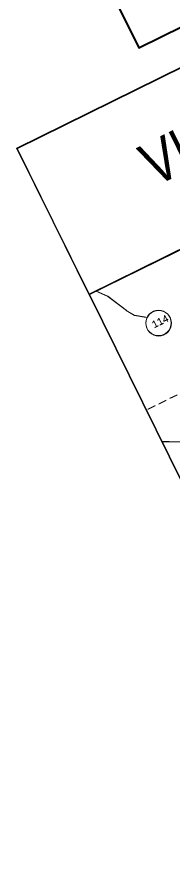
# Model space of a CAD drawing. Extents: x 2356606 to 2371222, y 6973096 to 6982644.
# Drawn here: x 2356946 to 2357060, y 6973388 to 6974009 of the extents above; entities that cross this region are included whole.
import ezdxf

# ---------------------------------------------------------------- set-up
doc = ezdxf.new("R2010")
doc.units = 0
doc.header["$LTSCALE"] = 2
doc.linetypes.add('MEDIUM_DASHED', pattern=[4.5, 3, -1.5])
doc.layers.add('62', color=7, linetype='Continuous', lineweight=13)
doc.layers.add('63', color=7, linetype='Continuous', lineweight=13)

msp = doc.modelspace()

# ---------------------------------------------------------------- linework, layer by layer
at = {"layer": '62', "lineweight": 25}
msp.add_line((2356999.05, 6973805.301), (2357402.214, 6974004.278), dxfattribs=at)
at = {"layer": '62', "linetype": 'MEDIUM_DASHED'}
msp.add_line((2357443, 6973918.637), (2357041.025, 6973720.25), dxfattribs=at)
at = {"layer": '62'}
for p, q in [((2357026.111, 6973793.69), (2357032.35, 6973789.843)), ((2357032.35, 6973789.843), (2357040.946, 6973788.391)), ((2357052.469, 6973697.063), (2357057.876, 6973697.099)), ((2357057.876, 6973697.099), (2357066.447, 6973696.813))]:
    msp.add_line(p, q, dxfattribs=at)
at = {"layer": '62', "lineweight": 25}
for points in [[(2356999.05, 6973805.301), (2356946.031, 6973912.733), (2357348.892, 6974111.56), (2357402.214, 6974004.278)], [(2356999.05, 6973805.301), (2357204.965, 6973388.075), (2357608.13, 6973587.05), (2357402.214, 6974004.278)]]:
    msp.add_lwpolyline(points, dxfattribs=at)
at = {"layer": '62', "lineweight": 40}
msp.add_lwpolyline([(2357000.317, 6974057.993), (2357035.475, 6973986.756), (2357293.714, 6974114.204)], dxfattribs=at)
at = {"layer": '62'}
msp.add_lwpolyline([(2357003.914, 6973807.702), (2357012.762, 6973803.815), (2357026.353, 6973793.608)], dxfattribs=at)
msp.add_circle((2357050.053, 6973784.204), 9.364, dxfattribs=at)
at = {"layer": '63', "lineweight": 25}
msp.add_line((2356998.92, 6973805.564), (2357402.084, 6974004.541), dxfattribs=at)
at = {"layer": '63', "linetype": 'MEDIUM_DASHED'}
msp.add_line((2357442.87, 6973918.9), (2357040.895, 6973720.513), dxfattribs=at)
at = {"layer": '63'}
for p, q in [((2357025.981, 6973793.953), (2357032.22, 6973790.106)), ((2357032.22, 6973790.106), (2357040.816, 6973788.654)), ((2357052.339, 6973697.326), (2357057.746, 6973697.362)), ((2357057.746, 6973697.362), (2357066.317, 6973697.076))]:
    msp.add_line(p, q, dxfattribs=at)
at = {"layer": '63', "lineweight": 25}
for points in [[(2356998.92, 6973805.564), (2356945.901, 6973912.996), (2357348.762, 6974111.823), (2357402.084, 6974004.541)], [(2356998.92, 6973805.564), (2357204.835, 6973388.338), (2357608, 6973587.313), (2357402.084, 6974004.541)]]:
    msp.add_lwpolyline(points, dxfattribs=at)
at = {"layer": '63', "lineweight": 40}
msp.add_lwpolyline([(2357000.317, 6974057.993), (2357035.475, 6973986.756), (2357293.714, 6974114.204)], dxfattribs=at)
at = {"layer": '63'}
msp.add_lwpolyline([(2357003.784, 6973807.965), (2357012.632, 6973804.078), (2357026.223, 6973793.871)], dxfattribs=at)
msp.add_circle((2357049.923, 6973784.467), 9.364, dxfattribs=at)

# ---------------------------------------------------------------- texts
at = {"layer": '62'}
for s, height, width, p in [('VICINITY MAP', 31.45, 0.85, (2357047.141, 6973884.294)), ('114', 5.099, 1.1, (2357046.713, 6973780.373))]:
    msp.add_text(s, height=height, rotation=26.268, dxfattribs=dict(at, width=width)).set_placement(p)
at = {"layer": '63'}
for s, height, width, p in [('VICINITY MAP', 31.45, 0.85, (2357047.011, 6973884.558)), ('114', 5.099, 1.1, (2357046.583, 6973780.637))]:
    msp.add_text(s, height=height, rotation=26.268, dxfattribs=dict(at, width=width)).set_placement(p)

doc.saveas('drawing.dxf')
